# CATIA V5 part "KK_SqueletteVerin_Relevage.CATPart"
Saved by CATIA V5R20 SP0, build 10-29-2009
Part number: Squelette_corps_verin_de_relevage
Bounding box of the stored display mesh (mm): x -288 to -266.861, y -200 to 200, z -671.811 to 512
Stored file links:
  G:\Khaled_CFAO_2011\ST2M\ST2M_GR2\aboulegue\Khaled\CAD_thinkMOTION\KK_SqueletteVerin_Relevage.CATPart
  G:\Khaled_CFAO_2011\ST2M\ST2M_GR2\aboulegue\Khaled\CAD_thinkMOTION\KK_Train_Atterrissage.CATProduct
  G:\Khaled_CFAO_2011\ST2M\ST2M_GR2\aboulegue\CFAO_aboulegue\CFAO_aboulegue_fichiers_catia\Squelette_general.CATPart
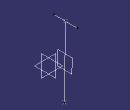
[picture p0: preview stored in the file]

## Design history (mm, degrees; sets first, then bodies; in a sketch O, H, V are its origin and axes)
Set1
  Point1 "Point.11": linked copy from another document
  Point2 "Point.19": linked copy from another document
  Plane1 "Plan reference 2": linked copy from another document
Set2 "Set squelette corps verin de relevage"
  Line1: type PtPt, FirstPoint Point1, SecondPoint Point2
  Line2: type Normal, RefPoint Point1, RefSkin Plane1, Start -200, End 200
  Plane2 "Plan de reference corps verin de relevage": type 2Lines, Element1 Line1, Element2 Line2
Body1 (main body)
